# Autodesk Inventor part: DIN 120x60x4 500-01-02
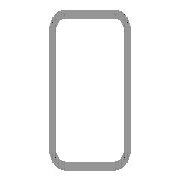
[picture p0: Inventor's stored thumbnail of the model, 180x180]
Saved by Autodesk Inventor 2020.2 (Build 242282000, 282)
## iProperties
Manager: www.cadconsulting.pl
Company: Fabian Stasiak CAD Consulting
Created: 2015-02
Part Number: DIN 120x60x4 500-01-02
Material: Stal
Description: Rurki stalowe o przekroju prostokątnym formowane na gorąco
Document SubType Name: Modellieren
Standard: DIN
Designer: F.Stasiak
Standards Organization: DIN
Language: pl-PL
Size Designation: 120x60x4
Categories: <MemberInstance><Categories><Category DisplayName="Kształtowniki konstrukcyjne" InternalName="089c4875-fa83-4c05-b084-43b9cc11f5ed" Mnemonic="GRDR"><CategoryPar
Stock Number: 120x60x4
Density: 7.85 g/cm^3
Appearance: Płyta
IsCustomPart: 1
G_L: 970,000 mm
G_W: 60,000 mm
G_H: 120,000 mm
+8458E4FF-DFCE-441F-97C4-4D3776AB817A+CUTDETAIL1: Wytnij
+B13AA665-A8A2-46E3-9D95-F9C71092F1DE+CUTDETAIL2: Wytnij
_CCFamilyMember: 190
_CCFamilyDisplayName: DIN 59410 (Prostokąt) - Rurki stalowe o przekroju prostokątnym formowane na gorąco — Standard DIN 59410 (Prostokąt) został wycofany i zastąpiony przez standard 
_FrameMemberDoc: Frame Member File
_Version: 15.0.0
_GetPNFromCC: 1
Author: F.Stasiak
Subject: Zbiór ćwiczeń. Autodesk Inventor 2020. Kurs podstawowy
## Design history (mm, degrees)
node "Płaszczyzna początkowa"
node "Płaszczyzna końcowa"
sketch "Szkic"
  geometry: L1 (-22, 60)-(22, 60); L2 (30, 52)-(30, -52); L3 (22, -60)-(-22, -60); L4 (-30, -52)-(-30, 52); L5 (-44.32, 0)-(44.32, 0) reference; L6 (0, -86.32)-(0, 86.32) reference; L7 (-22, 56)-(22, 56); L8 (26, 52)-(26, -52); L9 (22, -56)-(-22, -56); L10 (-26, -52)-(-26, 52); A1 r 8 centre (-22, 52) between (-22, 60) and (-30, 52); A2 r 8 centre (22, 52) between (30, 52) and (22, 60); A3 r 8 centre (22, -52) between (22, -60) and (30, -52); A4 r 8 centre (-22, -52) between (-30, -52) and (-22, -60); A5 r 4 centre (-22, 52) between (-22, 56) and (-26, 52); A6 r 4 centre (22, 52) between (26, 52) and (22, 56); A7 r 4 centre (22, -52) between (22, -56) and (26, -52); A8 r 4 centre (-22, -52) between (-26, -52) and (-22, -56); 3 further points
  constraints: 16 end point, 16 point on circle, 8 centre point, 8 tangent, 6 point on line, 4 parallel, 3 equal radius, 2 perpendicular, 1 horizontal, 7 other
  dimensions: "b" = 60 distance of point (-30, 60) point (30, 60); "ParH" = 120 distance of point (30, 60) point (30, -60); "msp_r" = 8 radius of A1 (= 2 x ParT); "d8" = 30 distance between parallel lines of L4 L6 (= 0.5 x b); "d9" = 60 distance between parallel lines of L5 L1 (= 0.5 x ParH); "d10" = 4 distance between parallel lines of L4 L10 (= ParT)
extrude "Bryła" new body sketch "Szkic" taper "d4" = 0 deg; stored distance "NLG" = 10
node "Driven Length"
  sketch "Sketch2"
    geometry: L1 (0, 0)-(10, 0) reference
    constraints: 2 end point, 1 horizontal
  workplane "Work Plane3"
  sketch "Sketch3"
    geometry: L1 (-2, 60)-(12, 60) reference; L2 (-2, 1030)-(12, 1030) reference
    dimensions: "d14" = 970 distance between parallel lines of L1 L2 (derived)
node "Płaszczyzna konstrukcyjna4"
feature "Podział1"
node "Płaszczyzna konstrukcyjna5"
feature "Podział2"
body "Solid1"
other parameters: "ParT" = 4, "G_L" = 970 (= d14) [user parameter], "d13" = 90 deg
